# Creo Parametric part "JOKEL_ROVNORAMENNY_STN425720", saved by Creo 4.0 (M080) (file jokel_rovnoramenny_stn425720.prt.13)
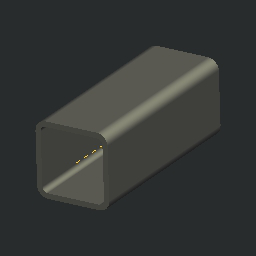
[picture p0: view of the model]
Units: Custom; MM, KILOGRAM, SECS
Materials in the file: OCEL_N

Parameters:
  NORMINFO = "Quadrat- und Rechteck-Hohlprofile (warmgefertigt, nahtlos oder geschweißt)"
  WY_CCM = "4.83"
  WX_CCM = "4.83"
  N_T = "9"
  B_T = "2.9"
  V_DICKE = "2"
  N_DICKE = "9"
  B_DICKE = "2.9"
  V_L = "100"
  B_L = "100"
  KATEGORIE = "0"
  DESIGNER = "."
  DATE = "."
  FORMAT = "."
  MOD_INDEX_1 = "."
  MOD_INDEX_2 = "."
  MOD_INDEX_3 = "."
  MOD_INDEX_4 = "."
  MOD_INDEX_5 = "."
  MOD_INDEX_6 = "."
  MOD_INDEX_7 = "."
  MOD_INDEX_8 = "."
  MOD_NOTE_1 = "."
  MOD_NOTE_2 = "."
  MOD_NOTE_3 = "."
  MOD_NOTE_4 = "."
  MOD_NOTE_5 = "."
  MOD_NOTE_6 = "."
  MOD_NOTE_7 = "."
  MOD_NOTE_8 = "."
  MOD_DATE_1 = "."
  MOD_DATE_2 = "."
  MOD_DATE_3 = "."
  MOD_DATE_4 = "."
  MOD_DATE_5 = "."
  MOD_DATE_6 = "."
  MOD_DATE_7 = "."
  MOD_DATE_8 = "."
  MOD_NAME_1 = "."
  MOD_NAME_2 = "."
  MOD_NAME_3 = "."
  MOD_NAME_4 = "."
  MOD_NAME_5 = "."
  MOD_NAME_6 = "."
  MOD_NAME_7 = "."
  MOD_NAME_8 = "."
  NAZOV = "JOKEL_ROVNORAMENNY_STN425720"
  ROZMER = "TR4HR 40x40x2.9x100"
  NORMA = "STN 42 5720"
  HMOTNOST_HR = "."
  MATERIAL_ZAKL = "."
  PTC_MATERIAL_NAME = "OCEL_N"

Other parameters: L, B, H, T, HMOTNOST, HUSTOTA, HMOTNOST_1, D19, D20, D23, D24

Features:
  1. datum plane "Y-Y"
  2. datum plane "X-X"
  3. datum plane "Z-Z"
  4. coordinate system
  5. datum axis
  6. datum axis
  7. datum axis
  8. protrusion
  9. curve

Other named items: ZZ, XX, YY, CS0

Named dimensions: Radius, Hoehe, Dicke, Laenge, Breite, laenge_nf

Layers: BEZUG, BEZUGSACHSEN, PLAZIERUNG, PROFIL_NEUTRALE_FASER

Notes: Hohlprofil | HP 40x40x2.9x100 DIN 59410 | Gewicht:  | 0.321 | Widerstandsmoment-Wx:  | 4.83 |  cm³ | Widerstandsmoment-Wy:  | 4.83 |  cm³ | Querschnittsflaeche-A:  |  cm²

Family table entries: GENERIC, JOKEL_TR4HR_40X2_9, JOKEL_ROVNORAMENNY_STN425720, value(d_val), 2/D, value(s_val), 4.830, 34.830, 34.23, value(i_val), JOKEL_TR4HR_40X4, JOKEL_ROVNORAMENNY_STN425720, !/D, 2/D, "6.050, 36.050, 35.62, JOKEL_TR4HR_50X2_9, JOKEL_ROVNORAMENNY_STN425720, !/I, 2/I, "7.940, 37.940, 35.39, JOKEL_TR4HR_50X4, JOKEL_ROVNORAMENNY_STN425720, !/I, 2/I, "10.100, 310.100, 37.22, JOKEL_TR4HR_50X5, JOKEL_ROVNORAMENNY_STN425720, !/I, 2/I, "11, 311, 37.8, JOKEL_TR4HR_60X2_9, JOKEL_ROVNORAMENNY_STN425720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

Surfaces: 10 plane, 8 cylinder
